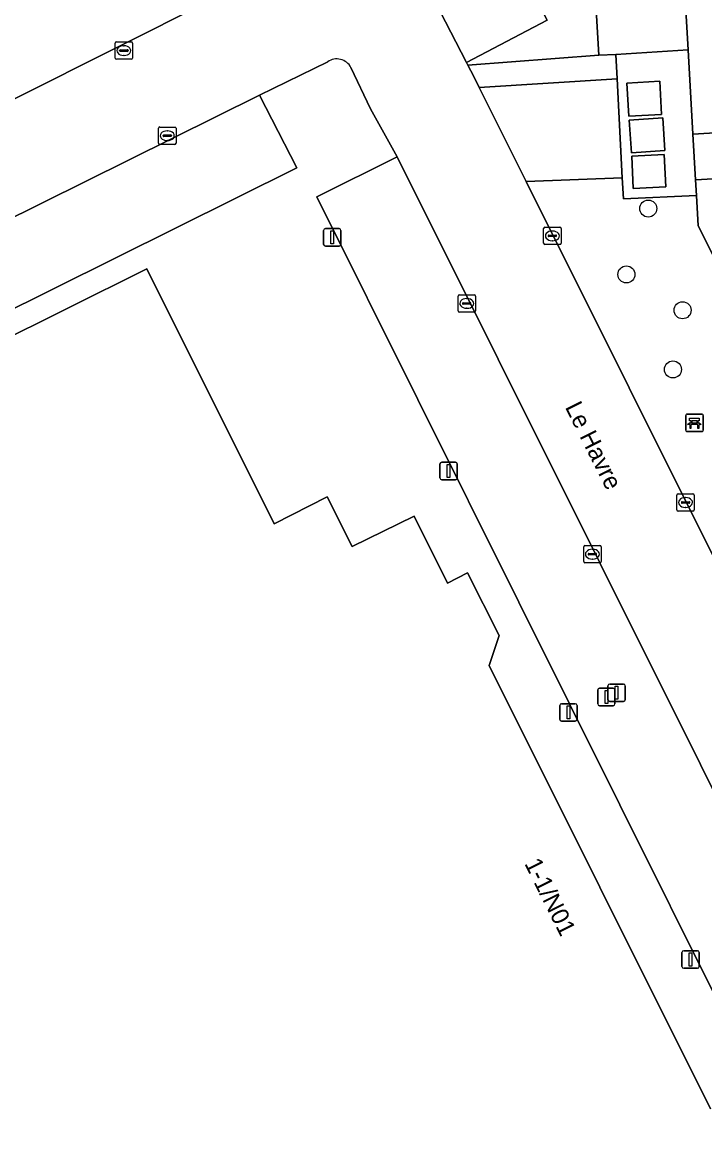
# Model space of a CAD drawing. Extents: x 158455 to 159797, y 387218 to 388672.
# Drawn here: x 158997.4 to 159036.6, y 387592.7 to 387656.2 of the extents above; entities that cross this region are included whole.
import ezdxf

# ---------------------------------------------------------------- set-up
doc = ezdxf.new("R2010")
doc.units = 0
for name, color, linetype in [('IMGEO_Bank', 7, 'Continuous'), ('IMGEO_Berm_groen', 7, 'Continuous'), ('IMGEO_Boom', 7, 'Continuous'), ('IMGEO_Groenvoorziening', 7, 'Continuous'), ('IMGEO_Kolk', 7, 'Continuous'), ('IMGEO_Lichtmast', 7, 'Continuous'), ('IMGEO_Openbare_ruimte_label', 7, 'Continuous'), ('IMGEO_Pand', 7, 'Continuous'), ('IMGEO_Pand_nummerreeks', 7, 'Continuous'), ('IMGEO_Parkeervlak_open', 7, 'Continuous'), ('IMGEO_Rijbaan_lokaal_open', 7, 'Continuous'), ('IMGEO_Voetpad_gesloten', 7, 'Continuous'), ('IMGEO_Voetpad_open', 7, 'Continuous')]:
    doc.layers.add(name, color=color, linetype=linetype)

msp = doc.modelspace()

# ---------------------------------------------------------------- linework, layer by layer
at = {"layer": 'IMGEO_Bank'}
for p, q in [((159035.608, 387633.656), (159036.449, 387633.656)), ((159036.449, 387633.656), (159035.608, 387633.656)), ((159035.533, 387632.731), (159035.533, 387633.572)), ((159035.533, 387633.572), (159035.533, 387632.731)), ((159036.23, 387633.054), (159035.837, 387633.054)), ((159035.842, 387633.162), (159035.842, 387633.268)), ((159035.886, 387633.268), (159035.886, 387633.162)), ((159036.174, 387633.274), (159035.892, 387633.274)), ((159035.892, 387633.156), (159036.174, 387633.156)), ((159036.18, 387633.162), (159036.18, 387633.268)), ((159036.224, 387633.268), (159036.224, 387633.162)), ((159036.533, 387633.581), (159036.533, 387632.74)), ((159036.533, 387632.74), (159036.533, 387633.581)), ((159036.458, 387632.656), (159035.617, 387632.656)), ((159035.617, 387632.656), (159036.458, 387632.656))]:
    msp.add_line(p, q, dxfattribs=at)
for points in [[(159035.78, 387633.054), (159035.638, 387633.054), (159035.75, 387633.156), (159035.836, 387633.156)], [(159035.836, 387633.274), (159035.75, 387633.274), (159035.75, 387633.435), (159036.313, 387633.435), (159036.313, 387633.274), (159036.23, 387633.274)], [(159035.83, 387633.047), (159035.83, 387632.84), (159035.787, 387632.84), (159035.787, 387633.047)], [(159036.23, 387633.156), (159036.313, 387633.156), (159036.425, 387633.054), (159036.286, 387633.054)], [(159036.28, 387633.047), (159036.28, 387632.84), (159036.236, 387632.84), (159036.236, 387633.047)]]:
    msp.add_lwpolyline(points, dxfattribs=at)
for centre, radius, start, end in [((159035.611, 387633.578), 0.0779, 92.4484, 184.28452), ((159035.611, 387633.578), 0.0779, 92.4484, 184.28452), ((159036.455, 387633.578), 0.0779, 2.4484, 94.28452), ((159036.455, 387633.578), 0.0779, 2.4484, 94.28452), ((159035.78, 387633.047), 0.00671, 2.89567, 87.10433), ((159035.837, 387633.047), 0.00671, 92.89567, 177.10433), ((159035.835, 387633.267), 0.00671, 2.89567, 87.10433), ((159035.835, 387633.163), 0.00671, 272.89567, 357.10433), ((159035.892, 387633.267), 0.00671, 92.89567, 177.10433), ((159035.892, 387633.163), 0.00671, 182.89567, 267.10433), ((159036.174, 387633.267), 0.00671, 2.89567, 87.10433), ((159036.174, 387633.163), 0.00671, 272.89567, 357.10433), ((159036.231, 387633.267), 0.00671, 92.89567, 177.10433), ((159036.231, 387633.163), 0.00671, 182.89567, 267.10433), ((159036.229, 387633.047), 0.00671, 2.89567, 87.10433), ((159036.286, 387633.047), 0.00671, 92.89567, 177.10433), ((159035.611, 387632.734), 0.0779, 182.4484, 274.28452), ((159035.611, 387632.734), 0.0779, 182.4484, 274.28452), ((159036.455, 387632.734), 0.0779, 272.4484, 4.28452), ((159036.455, 387632.734), 0.0779, 272.4484, 4.28452)]:
    msp.add_arc(centre, radius, start, end, dxfattribs=at)
at = {"layer": 'IMGEO_Berm_groen'}
msp.add_lwpolyline([(159036.238, 387644.461), (159036.145, 387646.208), (159031.955, 387646.01), (159031.892, 387647.226), (159026.374, 387647.012), (159050.035, 387599.601), (159057.036, 387603.022)], close=True, dxfattribs=at)
at = {"layer": 'IMGEO_Boom'}
for centre in [(159033.385, 387645.456), (159032.127, 387641.675), (159035.354, 387639.618), (159034.801, 387636.223)]:
    msp.add_circle(centre, 0.489, dxfattribs=at)
at = {"layer": 'IMGEO_Groenvoorziening'}
msp.add_lwpolyline([(158998.218, 387702.266), (159002.859, 387704.646), (159004.655, 387701.145), (159010.796, 387689.174), (159011.185, 387688.416), (159012.911, 387685.05), (159010.362, 387683.742), (159013.639, 387677.25), (159016.097, 387678.445), (159027.579, 387656.258), (159022.951, 387653.842), (159023.029, 387653.691), (159030.54, 387654.257), (159027.452, 387707.106)], dxfattribs=at)
at = {"layer": 'IMGEO_Kolk'}
for p, q in [((159002.788, 387654.093), (159002.788, 387654.945)), ((159002.863, 387655.019), (159003.715, 387655.019)), ((159003.276, 387654.799), (159003.301, 387654.799)), ((159003.789, 387654.945), (159003.789, 387654.093)), ((159003.715, 387654.019), (159002.863, 387654.019)), ((159003.047, 387654.513), (159003.047, 387654.525)), ((159003.485, 387654.476), (159003.087, 387654.476)), ((159003.09, 387654.562), (159003.488, 387654.562)), ((159003.299, 387654.239), (159003.274, 387654.239)), ((159003.531, 387654.525), (159003.531, 387654.513)), ((159005.356, 387650.134), (159006.208, 387650.134)), ((159005.281, 387649.208), (159005.281, 387650.06)), ((159005.54, 387649.628), (159005.54, 387649.64)), ((159005.978, 387649.591), (159005.58, 387649.591)), ((159005.583, 387649.677), (159005.981, 387649.677)), ((159005.769, 387649.914), (159005.794, 387649.914)), ((159006.024, 387649.64), (159006.024, 387649.628)), ((159006.282, 387650.06), (159006.282, 387649.208)), ((159006.208, 387649.134), (159005.356, 387649.134)), ((159005.792, 387649.354), (159005.767, 387649.354)), ((159027.378, 387643.461), (159027.378, 387644.313)), ((159027.453, 387644.387), (159028.305, 387644.387)), ((159027.637, 387643.881), (159027.637, 387643.893)), ((159028.075, 387643.844), (159027.677, 387643.844)), ((159027.68, 387643.93), (159028.078, 387643.93)), ((159027.866, 387644.167), (159027.891, 387644.167)), ((159028.121, 387643.893), (159028.121, 387643.881)), ((159028.379, 387644.313), (159028.379, 387643.461)), ((159028.305, 387643.387), (159027.453, 387643.387)), ((159027.889, 387643.607), (159027.864, 387643.607)), ((159022.466, 387639.584), (159022.466, 387640.436)), ((159022.541, 387640.51), (159023.393, 387640.51)), ((159022.725, 387640.004), (159022.725, 387640.016)), ((159022.768, 387640.053), (159023.166, 387640.053)), ((159022.954, 387640.29), (159022.979, 387640.29)), ((159023.209, 387640.016), (159023.209, 387640.004)), ((159023.467, 387640.436), (159023.467, 387639.584)), ((159023.393, 387639.51), (159022.541, 387639.51)), ((159023.163, 387639.967), (159022.765, 387639.967)), ((159022.977, 387639.73), (159022.952, 387639.73)), ((159035.023, 387628.163), (159035.023, 387629.015)), ((159035.098, 387629.089), (159035.95, 387629.089)), ((159035.282, 387628.583), (159035.282, 387628.595)), ((159035.325, 387628.632), (159035.723, 387628.632)), ((159035.511, 387628.869), (159035.536, 387628.869)), ((159035.766, 387628.595), (159035.766, 387628.583)), ((159036.024, 387629.015), (159036.024, 387628.163)), ((159035.95, 387628.089), (159035.098, 387628.089)), ((159035.72, 387628.546), (159035.322, 387628.546)), ((159035.534, 387628.309), (159035.509, 387628.309)), ((159029.677, 387625.195), (159029.677, 387626.047)), ((159029.752, 387626.121), (159030.604, 387626.121)), ((159030.678, 387626.047), (159030.678, 387625.195)), ((159029.936, 387625.615), (159029.936, 387625.627)), ((159030.374, 387625.578), (159029.976, 387625.578)), ((159029.979, 387625.664), (159030.377, 387625.664)), ((159030.165, 387625.901), (159030.19, 387625.901)), ((159030.42, 387625.627), (159030.42, 387625.615)), ((159030.604, 387625.121), (159029.752, 387625.121)), ((159030.188, 387625.341), (159030.163, 387625.341))]:
    msp.add_line(p, q, dxfattribs=at)
for points in [[(159002.788, 387654.093), (159002.788, 387654.945)], [(159002.863, 387655.019), (159003.715, 387655.019)], [(159003.789, 387654.945), (159003.789, 387654.093)], [(159003.715, 387654.019), (159002.863, 387654.019)], [(159005.356, 387650.134), (159006.208, 387650.134)], [(159005.281, 387649.208), (159005.281, 387650.06)], [(159006.282, 387650.06), (159006.282, 387649.208)], [(159006.208, 387649.134), (159005.356, 387649.134)], [(159027.378, 387643.461), (159027.378, 387644.313)], [(159027.453, 387644.387), (159028.305, 387644.387)], [(159028.379, 387644.313), (159028.379, 387643.461)], [(159028.305, 387643.387), (159027.453, 387643.387)], [(159022.466, 387639.584), (159022.466, 387640.436)], [(159022.541, 387640.51), (159023.393, 387640.51)], [(159023.467, 387640.436), (159023.467, 387639.584)], [(159023.393, 387639.51), (159022.541, 387639.51)], [(159035.023, 387628.163), (159035.023, 387629.015)], [(159035.098, 387629.089), (159035.95, 387629.089)], [(159036.024, 387629.015), (159036.024, 387628.163)], [(159035.95, 387628.089), (159035.098, 387628.089)], [(159029.677, 387625.195), (159029.677, 387626.047)], [(159029.752, 387626.121), (159030.604, 387626.121)], [(159030.678, 387626.047), (159030.678, 387625.195)], [(159030.604, 387625.121), (159029.752, 387625.121)]]:
    msp.add_lwpolyline(points, dxfattribs=at)
for centre, radius, start, end in [((159002.865, 387654.943), 0.0765, 91.55205, 178.44795), ((159002.865, 387654.943), 0.0765, 91.55205, 178.44795), ((159003.713, 387654.943), 0.0765, 1.55205, 88.44795), ((159003.713, 387654.943), 0.0765, 1.55205, 88.44795), ((159002.865, 387654.095), 0.0765, 181.55205, 268.44795), ((159002.865, 387654.095), 0.0765, 181.55205, 268.44795), ((159003.087, 387654.522), 0.0403, 85.87752, 175.75265), ((159003.084, 387654.512), 0.0366, 178.93798, 274.71019), ((159003.488, 387654.519), 0.043, 264.86636, 352.45326), ((159003.492, 387654.524), 0.0386, 1.73085, 96.63898), ((159003.713, 387654.095), 0.0765, 271.55205, 358.44795), ((159003.713, 387654.095), 0.0765, 271.55205, 358.44795), ((159005.358, 387650.058), 0.0765, 91.55205, 178.44795), ((159005.358, 387650.058), 0.0765, 91.55205, 178.44795), ((159006.206, 387650.058), 0.0765, 1.55205, 88.44795), ((159006.206, 387650.058), 0.0765, 1.55205, 88.44795), ((159005.58, 387649.637), 0.0403, 85.87752, 175.75265), ((159005.577, 387649.627), 0.0366, 178.93798, 274.71019), ((159005.981, 387649.634), 0.043, 264.86636, 352.45326), ((159005.985, 387649.639), 0.0386, 1.73085, 96.63898), ((159005.358, 387649.21), 0.0765, 181.55205, 268.44795), ((159005.358, 387649.21), 0.0765, 181.55205, 268.44795), ((159006.206, 387649.21), 0.0765, 271.55205, 358.44795), ((159006.206, 387649.21), 0.0765, 271.55205, 358.44795), ((159027.455, 387644.311), 0.0765, 91.55205, 178.44795), ((159027.455, 387644.311), 0.0765, 91.55205, 178.44795), ((159027.677, 387643.89), 0.0403, 85.87752, 175.75265), ((159027.674, 387643.88), 0.0366, 178.93798, 274.71019), ((159028.078, 387643.887), 0.043, 264.86636, 352.45326), ((159028.082, 387643.892), 0.0386, 1.73085, 96.63898), ((159028.303, 387644.311), 0.0765, 1.55205, 88.44795), ((159028.303, 387644.311), 0.0765, 1.55205, 88.44795), ((159027.455, 387643.463), 0.0765, 181.55205, 268.44795), ((159027.455, 387643.463), 0.0765, 181.55205, 268.44795), ((159028.303, 387643.463), 0.0765, 271.55205, 358.44795), ((159028.303, 387643.463), 0.0765, 271.55205, 358.44795), ((159022.543, 387640.434), 0.0765, 91.55205, 178.44795), ((159022.543, 387640.434), 0.0765, 91.55205, 178.44795), ((159022.765, 387640.013), 0.0403, 85.87752, 175.75265), ((159022.762, 387640.003), 0.0366, 178.93798, 274.71019), ((159023.166, 387640.01), 0.043, 264.86636, 352.45326), ((159023.17, 387640.015), 0.0386, 1.73085, 96.63898), ((159023.391, 387640.434), 0.0765, 1.55205, 88.44795), ((159023.391, 387640.434), 0.0765, 1.55205, 88.44795), ((159022.543, 387639.586), 0.0765, 181.55205, 268.44795), ((159022.543, 387639.586), 0.0765, 181.55205, 268.44795), ((159023.391, 387639.586), 0.0765, 271.55205, 358.44795), ((159023.391, 387639.586), 0.0765, 271.55205, 358.44795), ((159035.1, 387629.013), 0.0765, 91.55205, 178.44795), ((159035.1, 387629.013), 0.0765, 91.55205, 178.44795), ((159035.322, 387628.592), 0.0403, 85.87752, 175.75265), ((159035.319, 387628.582), 0.0366, 178.93798, 274.71019), ((159035.723, 387628.589), 0.043, 264.86636, 352.45326), ((159035.727, 387628.594), 0.0386, 1.73085, 96.63898), ((159035.948, 387629.013), 0.0765, 1.55205, 88.44795), ((159035.948, 387629.013), 0.0765, 1.55205, 88.44795), ((159035.1, 387628.165), 0.0765, 181.55205, 268.44795), ((159035.1, 387628.165), 0.0765, 181.55205, 268.44795), ((159035.948, 387628.165), 0.0765, 271.55205, 358.44795), ((159035.948, 387628.165), 0.0765, 271.55205, 358.44795), ((159029.754, 387626.045), 0.0765, 91.55205, 178.44795), ((159029.754, 387626.045), 0.0765, 91.55205, 178.44795), ((159030.602, 387626.045), 0.0765, 1.55205, 88.44795), ((159030.602, 387626.045), 0.0765, 1.55205, 88.44795), ((159029.976, 387625.624), 0.0403, 85.87752, 175.75265), ((159029.973, 387625.614), 0.0366, 178.93798, 274.71019), ((159030.377, 387625.621), 0.043, 264.86636, 352.45326), ((159030.381, 387625.626), 0.0386, 1.73085, 96.63898), ((159029.754, 387625.197), 0.0765, 181.55205, 268.44795), ((159029.754, 387625.197), 0.0765, 181.55205, 268.44795), ((159030.602, 387625.197), 0.0765, 271.55205, 358.44795), ((159030.602, 387625.197), 0.0765, 271.55205, 358.44795)]:
    msp.add_arc(centre, radius, start, end, dxfattribs=at)
for centre, major_axis, ratio, start_param, end_param in [((159003.275, 387654.519), (-0.387, 0.002), 0.722429, 4.712389, 7.853982), ((159003.3, 387654.519), (-0.39, 0.002), 0.717154, 1.570796, 4.712389), ((159005.768, 387649.634), (-0.387, 0.002), 0.722429, 4.712389, 7.853982), ((159005.793, 387649.634), (-0.39, 0.002), 0.717154, 1.570796, 4.712389), ((159027.865, 387643.887), (-0.387, 0.002), 0.722429, 4.712389, 7.853982), ((159027.89, 387643.887), (-0.39, 0.002), 0.717154, 1.570796, 4.712389), ((159022.953, 387640.01), (-0.387, 0.002), 0.722429, 4.712389, 7.853982), ((159022.978, 387640.01), (-0.39, 0.002), 0.717154, 1.570796, 4.712389), ((159035.51, 387628.589), (-0.387, 0.002), 0.722429, 4.712389, 7.853982), ((159035.535, 387628.589), (-0.39, 0.002), 0.717154, 1.570796, 4.712389), ((159030.164, 387625.621), (-0.387, 0.002), 0.722429, 4.712389, 7.853982), ((159030.189, 387625.621), (-0.39, 0.002), 0.717154, 1.570796, 4.712389)]:
    msp.add_ellipse(centre, major_axis=major_axis, ratio=ratio, start_param=start_param, end_param=end_param, dxfattribs=at)
at = {"layer": 'IMGEO_Lichtmast'}
for p, q in [((159014.753, 387643.401), (159014.753, 387644.201)), ((159014.753, 387644.201), (159014.753, 387643.401)), ((159014.853, 387644.301), (159015.643, 387644.301)), ((159015.643, 387644.301), (159014.853, 387644.301)), ((159015.743, 387644.201), (159015.743, 387643.401)), ((159015.743, 387643.401), (159015.743, 387644.201)), ((159015.643, 387643.301), (159014.853, 387643.301)), ((159014.853, 387643.301), (159015.643, 387643.301)), ((159021.429, 387629.997), (159021.429, 387630.797)), ((159021.429, 387630.797), (159021.429, 387629.997)), ((159021.529, 387630.897), (159022.319, 387630.897)), ((159022.319, 387630.897), (159021.529, 387630.897)), ((159022.419, 387630.797), (159022.419, 387629.997)), ((159022.419, 387629.997), (159022.419, 387630.797)), ((159022.319, 387629.897), (159021.529, 387629.897)), ((159021.529, 387629.897), (159022.319, 387629.897)), ((159030.483, 387617.029), (159030.483, 387617.829)), ((159030.483, 387617.829), (159030.483, 387617.029)), ((159030.583, 387617.929), (159031.373, 387617.929)), ((159031.373, 387617.929), (159030.583, 387617.929)), ((159031.069, 387617.268), (159031.069, 387618.068)), ((159031.069, 387618.068), (159031.069, 387617.268)), ((159031.169, 387618.168), (159031.959, 387618.168)), ((159031.959, 387618.168), (159031.169, 387618.168)), ((159031.473, 387617.829), (159031.473, 387617.029)), ((159031.473, 387617.029), (159031.473, 387617.829)), ((159032.059, 387618.068), (159032.059, 387617.268)), ((159032.059, 387617.268), (159032.059, 387618.068)), ((159031.959, 387617.168), (159031.169, 387617.168)), ((159031.169, 387617.168), (159031.959, 387617.168)), ((159028.307, 387616.142), (159028.307, 387616.942)), ((159028.307, 387616.942), (159028.307, 387616.142)), ((159028.407, 387617.042), (159029.197, 387617.042)), ((159029.197, 387617.042), (159028.407, 387617.042)), ((159029.297, 387616.942), (159029.297, 387616.142)), ((159029.297, 387616.142), (159029.297, 387616.942)), ((159031.373, 387616.929), (159030.583, 387616.929)), ((159030.583, 387616.929), (159031.373, 387616.929)), ((159029.197, 387616.042), (159028.407, 387616.042)), ((159028.407, 387616.042), (159029.197, 387616.042)), ((159035.316, 387601.964), (159035.316, 387602.764)), ((159035.316, 387602.764), (159035.316, 387601.964)), ((159035.416, 387602.864), (159036.206, 387602.864)), ((159036.206, 387602.864), (159035.416, 387602.864)), ((159036.306, 387602.764), (159036.306, 387601.964)), ((159036.306, 387601.964), (159036.306, 387602.764)), ((159036.206, 387601.864), (159035.416, 387601.864)), ((159035.416, 387601.864), (159036.206, 387601.864))]:
    msp.add_line(p, q, dxfattribs=at)
for points in [[(159015.173, 387644.176), (159015.323, 387644.176), (159015.323, 387643.426), (159015.173, 387643.426), (159015.173, 387644.176)], [(159021.849, 387630.772), (159021.999, 387630.772), (159021.999, 387630.022), (159021.849, 387630.022), (159021.849, 387630.772)], [(159030.903, 387617.804), (159031.053, 387617.804), (159031.053, 387617.054), (159030.903, 387617.054), (159030.903, 387617.804)], [(159031.489, 387618.043), (159031.639, 387618.043), (159031.639, 387617.293), (159031.489, 387617.293), (159031.489, 387618.043)], [(159028.727, 387616.917), (159028.877, 387616.917), (159028.877, 387616.167), (159028.727, 387616.167), (159028.727, 387616.917)], [(159035.736, 387602.739), (159035.886, 387602.739), (159035.886, 387601.989), (159035.736, 387601.989), (159035.736, 387602.739)]]:
    msp.add_lwpolyline(points, dxfattribs=at)
for centre, start, end in [((159014.853, 387644.201), 90, 180), ((159014.853, 387644.201), 90, 180), ((159015.643, 387644.201), 0, 90), ((159015.643, 387644.201), 360, 90), ((159014.853, 387643.401), 180, 270), ((159014.853, 387643.401), 180, 270), ((159015.643, 387643.401), 270, 0), ((159015.643, 387643.401), 270, 0), ((159021.529, 387630.797), 90, 180), ((159021.529, 387630.797), 90, 180), ((159022.319, 387630.797), 0, 90), ((159022.319, 387630.797), 360, 90), ((159021.529, 387629.997), 180, 270), ((159021.529, 387629.997), 180, 270), ((159022.319, 387629.997), 270, 0), ((159022.319, 387629.997), 270, 0), ((159030.583, 387617.829), 90, 180), ((159030.583, 387617.829), 90, 180), ((159031.169, 387618.068), 90, 180), ((159031.169, 387618.068), 90, 180), ((159031.373, 387617.829), 0, 90), ((159031.373, 387617.829), 360, 90), ((159031.959, 387618.068), 0, 90), ((159031.959, 387618.068), 360, 90), ((159031.169, 387617.268), 180, 270), ((159031.169, 387617.268), 180, 270), ((159031.959, 387617.268), 270, 0), ((159031.959, 387617.268), 270, 0), ((159028.407, 387616.942), 90, 180), ((159028.407, 387616.942), 90, 180), ((159029.197, 387616.942), 0, 90), ((159029.197, 387616.942), 360, 90), ((159030.583, 387617.029), 180, 270), ((159030.583, 387617.029), 180, 270), ((159031.373, 387617.029), 270, 0), ((159031.373, 387617.029), 270, 0), ((159028.407, 387616.142), 180, 270), ((159028.407, 387616.142), 180, 270), ((159029.197, 387616.142), 270, 0), ((159029.197, 387616.142), 270, 0), ((159035.416, 387602.764), 90, 180), ((159035.416, 387602.764), 90, 180), ((159036.206, 387602.764), 0, 90), ((159036.206, 387602.764), 360, 90), ((159035.416, 387601.964), 180, 270), ((159035.416, 387601.964), 180, 270), ((159036.206, 387601.964), 270, 0), ((159036.206, 387601.964), 270, 0)]:
    msp.add_arc(centre, 0.1, start, end, dxfattribs=at)
at = {"layer": 'IMGEO_Pand'}
msp.add_lwpolyline([(159036.947, 387593.79), (159024.254, 387619.231), (159024.817, 387620.962), (159023.01, 387624.548), (159021.858, 387623.967), (159019.945, 387627.812), (159016.396, 387626.055), (159014.949, 387628.907), (159011.917, 387627.37), (159004.608, 387641.996), (159000, 387639.704), (158969.841, 387624.709), (158982.888, 387598.642), (158974.258, 387594.339), (158989.066, 387564.615), (158980.49, 387560.322), (158984.967, 387551.32), (158993.663, 387555.669), (158995.069, 387552.858), (158986.374, 387548.51), (158990.195, 387540.846)], dxfattribs=at)
at = {"layer": 'IMGEO_Parkeervlak_open'}
for points in [[(159031.529, 387654.302), (159035.675, 387654.555), (159032.564, 387707.381), (159027.452, 387707.106), (159030.54, 387654.257)], [(159016.097, 387678.445), (159013.639, 387677.25), (159010.362, 387683.742), (159008.105, 387682.585), (159008.752, 387681.332), (159022.951, 387653.842), (159027.579, 387656.258)], [(159008.345, 387657.448), (159006.332, 387661.445), (158944.377, 387630.625), (158946.279, 387626.609), (158986.006, 387646.24)], [(159031.601, 387652.898), (159023.68, 387652.41), (159026.374, 387647.012), (159031.892, 387647.226)], [(159011.079, 387651.953), (158991.129, 387642.076), (158948.883, 387621.227), (158951.046, 387616.798), (158968.024, 387625.33), (159013.219, 387647.788)], [(159042.17, 387601.935), (159018.981, 387648.425), (159014.372, 387646.136), (159037.554, 387599.613)]]:
    msp.add_lwpolyline(points, close=True, dxfattribs=at)
at = {"layer": 'IMGEO_Rijbaan_lokaal_open'}
for points in [[(159032.373, 387709.804), (159032.564, 387707.381), (159035.675, 387654.555), (159035.934, 387649.722), (159041.984, 387650.094), (159041.814, 387652.914), (159039.302, 387695.754), (159038.868, 387703.16), (159038.012, 387717.992), (159037.915, 387719.107), (159000, 387716.875), (158991.471, 387716.373), (158991.475, 387715.921), (158992.385, 387700.116), (158992.424, 387699.679), (158991.942, 387699.057), (158982.246, 387694.247), (158955.393, 387680.776), (158954.104, 387680.116)], [(159026.374, 387647.012), (159023.68, 387652.41), (159023.367, 387653.037), (159023.029, 387653.691), (159022.951, 387653.842), (159008.752, 387681.332), (159008.105, 387682.585), (159000, 387698.276), (158998.996, 387700.221)], [(159012.199, 387659.391), (159008.345, 387657.448), (158986.006, 387646.24), (158946.279, 387626.609), (158948.883, 387621.227), (158991.129, 387642.076), (159011.079, 387651.953), (159014.987, 387653.88)], [(159016.32, 387653.549), (159017.451, 387651.175), (159018.981, 387648.425), (159042.17, 387601.935), (159048.183, 387589.84), (159059.923, 387566.332), (159060.876, 387564.44)], [(159065.368, 387568.879), (159051.06, 387597.547), (159050.035, 387599.601), (159026.374, 387647.012)], [(159054.656, 387621.191), (159052.206, 387626.058), (159043.202, 387644.022), (159042.221, 387645.918), (159042.168, 387647.445), (159036.101, 387647.097), (159036.145, 387646.208), (159036.238, 387644.461), (159057.036, 387603.022), (159058.095, 387600.913), (159072.299, 387572.612)]]:
    msp.add_lwpolyline(points, dxfattribs=at)
msp.add_lwpolyline([(159035.934, 387649.722), (159036.101, 387647.097), (159042.168, 387647.445), (159041.984, 387650.094)], close=True, dxfattribs=at)
msp.add_arc((159015.508, 387653.129), 0.914, 27.34869, 124.76094, dxfattribs=at)
at = {"layer": 'IMGEO_Voetpad_gesloten'}
for points in [[(159034.149, 387650.858), (159034.039, 387652.761), (159032.15, 387652.653), (159032.26, 387650.749)], [(159034.383, 387646.699), (159034.292, 387648.56), (159032.434, 387648.468), (159032.525, 387646.608)]]:
    msp.add_lwpolyline(points, close=True, dxfattribs=at)
at = {"layer": 'IMGEO_Voetpad_open'}
for points in [[(159031.529, 387654.302), (159030.54, 387654.257), (159023.029, 387653.691), (159023.367, 387653.037), (159023.68, 387652.41), (159031.601, 387652.898)], [(159035.934, 387649.722), (159035.675, 387654.555), (159031.529, 387654.302), (159031.601, 387652.898), (159031.892, 387647.226), (159031.955, 387646.01), (159036.145, 387646.208), (159036.101, 387647.097)], [(159034.149, 387650.858), (159032.26, 387650.749), (159032.15, 387652.653), (159034.039, 387652.761)], [(159034.337, 387648.777), (159034.217, 387650.653), (159032.296, 387650.53), (159032.416, 387648.654)], [(159032.416, 387648.654), (159032.296, 387650.53), (159034.217, 387650.653), (159034.337, 387648.777)], [(159034.383, 387646.699), (159032.525, 387646.608), (159032.434, 387648.468), (159034.292, 387648.56)]]:
    msp.add_lwpolyline(points, close=True, dxfattribs=at)
for points in [[(159014.987, 387653.88), (159011.079, 387651.953), (159013.219, 387647.788), (158968.024, 387625.33), (158951.046, 387616.798), (158951.609, 387615.644), (158969.841, 387624.709), (159000, 387639.704)], [(159060.876, 387564.44), (159059.923, 387566.332), (159055.289, 387564.036), (159043.577, 387587.533), (159048.183, 387589.84), (159042.17, 387601.935), (159037.554, 387599.613), (159014.372, 387646.136), (159018.981, 387648.425), (159017.451, 387651.175), (159016.32, 387653.549)], [(159000, 387639.704), (159004.608, 387641.996), (159011.917, 387627.37), (159014.949, 387628.907), (159016.396, 387626.055), (159019.945, 387627.812), (159021.858, 387623.967), (159023.01, 387624.548), (159024.817, 387620.962), (159024.254, 387619.231), (159036.947, 387593.79)]]:
    msp.add_lwpolyline(points, dxfattribs=at)
msp.add_arc((159015.508, 387653.129), 0.914, 27.34869, 124.76094, dxfattribs=at)

# ---------------------------------------------------------------- texts
at = {"layer": 'IMGEO_Openbare_ruimte_label'}
msp.add_text('Le Havre', height=1, rotation=296.6675, dxfattribs=at).set_placement((159028.587, 387634.062))
at = {"layer": 'IMGEO_Pand_nummerreeks'}
msp.add_text('1-1/N01', height=1, rotation=296.51548, dxfattribs=at).set_placement((159026.254, 387607.875))

doc.saveas('drawing.dxf')
